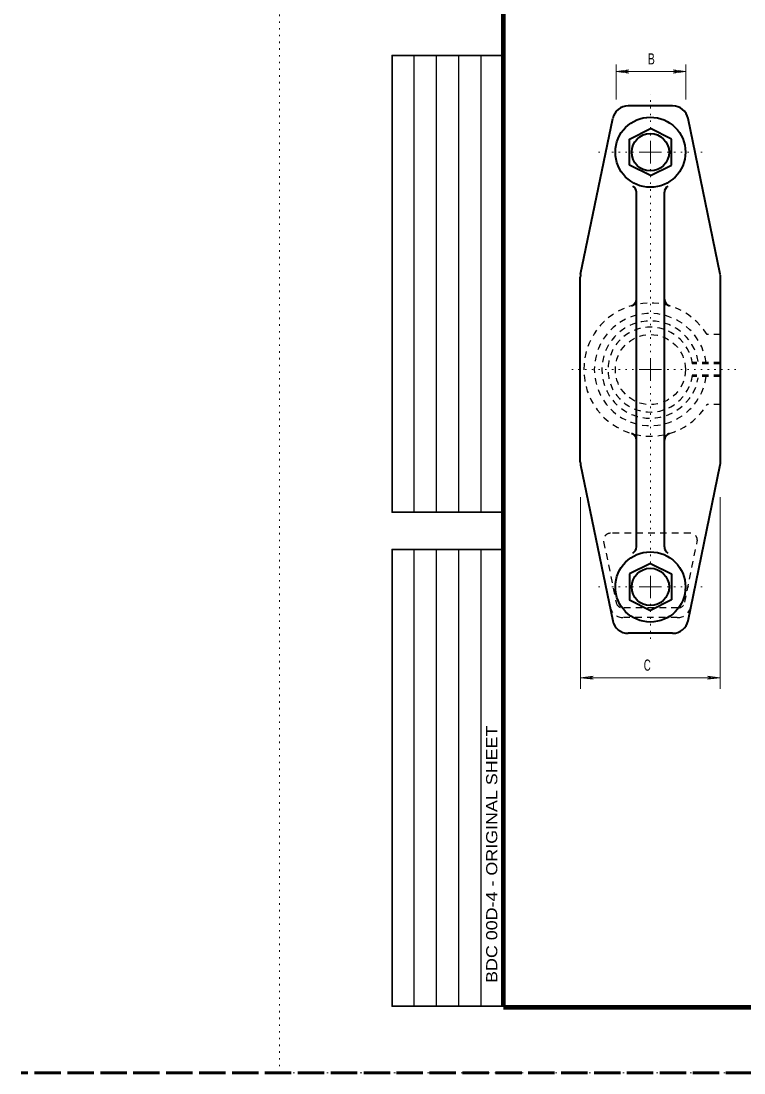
# Model space of a CAD drawing. Extents: x 312583 to 312854, y 144419 to 144597.
# Drawn here: x 312583.5 to 312632.9, y 144418.6 to 144490.5 of the extents above; entities that cross this region are included whole.
import ezdxf

# ---------------------------------------------------------------- set-up
doc = ezdxf.new("R2010")
doc.units = 0
doc.header["$LTSCALE"] = 0.3
for name, pattern in [('DOTTED', [1.5, 0.3, -1.2]), ('LONG_DASHED', [7.5, 6, -1.5]), ('SHORT_DASHED', [2.7, 1.5, -1.2])]:
    doc.linetypes.add(name, pattern=pattern)
for name, color, linetype, lineweight in [('1', 7, 'Continuous', 40), ('2', 7, 'Continuous', 13), ('62', 7, 'DOTTED', 13), ('63', 7, 'LONG_DASHED', 60)]:
    doc.layers.add(name, color=color, linetype=linetype, lineweight=lineweight)

msp = doc.modelspace()

# ---------------------------------------------------------------- linework, layer by layer
at = {"layer": '1', "lineweight": 25}
for p, q in [((312610.4087, 144456.901), (312610.4087, 144488.1192)), ((312611.9315, 144456.901), (312611.9315, 144488.1192)), ((312613.4543, 144456.901), (312613.4543, 144488.1192)), ((312614.9772, 144456.901), (312614.9772, 144488.1192)), ((312610.4087, 144423.1446), (312610.4087, 144454.3629)), ((312611.9315, 144423.1446), (312611.9315, 144454.3629)), ((312613.4543, 144423.1446), (312613.4543, 144454.3629)), ((312614.9772, 144423.1446), (312614.9772, 144454.3629))]:
    msp.add_line(p, q, dxfattribs=at)
at = {"layer": '1'}
for p, q in [((312628.0671, 144484.6708), (312625.0311, 144484.6708)), ((312621.7804, 144473.1632), (312623.9807, 144483.8122)), ((312631.3254, 144473.1632), (312629.1251, 144483.8122)), ((312627.9904, 144482.3938), (312626.5491, 144483.1145)), ((312627.9904, 144480.6228), (312627.9904, 144482.3938)), ((312626.5491, 144479.9022), (312625.1154, 144480.6228)), ((312626.5491, 144479.9022), (312627.9904, 144480.6228)), ((312625.5907, 144454.5332), (312625.5907, 144478.7752)), ((312627.5074, 144454.5332), (312627.5074, 144478.7752)), ((312621.7574, 144460.3368), (312621.7574, 144472.9638)), ((312631.3407, 144460.3368), (312631.3407, 144472.9638)), ((312621.7804, 144460.1452), (312623.9731, 144449.4885)), ((312629.1251, 144449.4885), (312631.3254, 144460.1452)), ((312626.5491, 144453.4062), (312625.1154, 144452.6855)), ((312626.5491, 144453.4062), (312627.9904, 144452.6855)), ((312627.9904, 144452.6855), (312627.9904, 144450.9068)), ((312627.9904, 144450.9068), (312626.5491, 144450.1938)), ((312628.0671, 144448.6298), (312625.0311, 144448.6298))]:
    msp.add_line(p, q, dxfattribs=at)
at = {"layer": '1', "linetype": 'SHORT_DASHED', "lineweight": 25}
for p, q in [((312631.3407, 144469.0462), (312630.4207, 144469.0462)), ((312631.3407, 144467.1295), (312629.4011, 144467.1295)), ((312631.3407, 144467.0375), (312629.4011, 144467.0375)), ((312631.3407, 144466.2708), (312629.4011, 144466.2708)), ((312631.3407, 144466.1712), (312629.4011, 144466.1712)), ((312631.3407, 144464.2545), (312630.4207, 144464.2545)), ((312629.2784, 144455.4685), (312623.8197, 144455.4685)), ((312623.3521, 144454.8935), (312624.2107, 144450.7458)), ((312628.8951, 144450.7458), (312629.7537, 144454.8935)), ((312628.4274, 144450.3625), (312624.6784, 144450.3625)), ((312628.3891, 144449.7032), (312624.7167, 144449.7032))]:
    msp.add_line(p, q, dxfattribs=at)
at = {"layer": '1', "lineweight": 158}
msp.add_line((312616.5, 144423.0846), (312849, 144423.0846), dxfattribs=at)
msp.add_lwpolyline([(312616.5, 144423.1446), (312616.5, 144585.0846), (312849, 144585.0846)], dxfattribs=at)
at = {"layer": '1', "lineweight": 35}
for points in [[(312616.5, 144456.901), (312608.8858, 144456.901), (312608.8858, 144488.1192), (312616.5, 144488.1192)], [(312616.5, 144423.1446), (312608.8858, 144423.1446), (312608.8858, 144454.3629), (312616.5, 144454.3629)]]:
    msp.add_lwpolyline(points, dxfattribs=at)
at = {"layer": '1'}
for points in [[(312625.1154, 144480.6228), (312625.1154, 144482.3938), (312626.5491, 144483.1145)], [(312625.1154, 144452.6855), (312625.1154, 144450.9145), (312626.5491, 144450.1938)]]:
    msp.add_lwpolyline(points, dxfattribs=at)
for centre, radius in [((312626.5491, 144481.5045), 2.3958), ((312626.5491, 144481.5045), 1.2773), ((312626.5491, 144451.7962), 2.3958), ((312626.5491, 144451.7962), 1.2773)]:
    msp.add_circle(centre, radius, dxfattribs=at)
at = {"layer": '1', "linetype": 'SHORT_DASHED', "lineweight": 25}
msp.add_circle((312626.5491, 144466.6503), 2.3958, dxfattribs=at)
at = {"layer": '1'}
for centre, radius, start, end in [((312625.0316, 144483.5927), 1.0781, 90, 168.33754), ((312628.0666, 144483.5927), 1.0781, 11.66246, 90), ((312625.1116, 144478.7732), 0.4792, 0, 60), ((312627.9866, 144478.7732), 0.4792, 120, 180), ((312622.7157, 144472.9656), 0.9583, 168.33293, 180), ((312630.3824, 144472.9656), 0.9583, 0, 11.66707), ((312625.1116, 144471.4739), 0.4792, 286.59504, 0), ((312627.9866, 144471.4739), 0.4792, 180, 253.40496), ((312625.1116, 144461.8268), 0.4792, 0, 73.40496), ((312627.9866, 144461.8268), 0.4792, 106.59504, 180), ((312622.7157, 144460.3387), 0.9583, 180, 191.64343), ((312630.3824, 144460.3387), 0.9583, 348.35657, 0), ((312625.1116, 144454.5275), 0.4792, 300, 0), ((312627.9866, 144454.5275), 0.4792, 180, 240), ((312625.0316, 144449.708), 1.0781, 191.65872, 270), ((312628.0665, 144449.708), 1.0781, 270, 348.34128)]:
    msp.add_arc(centre, radius, start, end, dxfattribs=at)
at = {"layer": '1', "linetype": 'SHORT_DASHED', "lineweight": 25}
for centre, radius, start, end in [((312626.5491, 144466.6503), 4.554, 31.74971, 328.25029), ((312626.5491, 144466.6503), 3.8333, 7.18188, 352.81924), ((312626.5491, 144466.6503), 3.3206, 9.58783, 350.40593), ((312626.5491, 144466.6503), 2.9011, 7.65517, 352.33031), ((312623.8189, 144454.9855), 0.4792, 90, 191.66303), ((312629.2792, 144454.9855), 0.4792, 348.33697, 90), ((312624.7141, 144450.6577), 0.9583, 191.66303, 270), ((312624.6744, 144450.8378), 0.4792, 191.66973, 270), ((312628.384, 144450.6577), 0.9583, 270, 348.33697), ((312628.4238, 144450.8378), 0.4792, 270, 348.33027)]:
    msp.add_arc(centre, radius, start, end, dxfattribs=at)
at = {"layer": '2'}
for p, q in [((312624.2031, 144485.1155), (312624.2031, 144487.4998)), ((312624.2031, 144487.0245), (312625.0694, 144487.1318)), ((312625.0694, 144487.1318), (312624.7934, 144487.0245)), ((312628.1054, 144487.1318), (312628.3814, 144487.0245)), ((312628.9717, 144487.0245), (312628.1054, 144487.1318)), ((312628.9717, 144485.1155), (312628.9717, 144487.4998)), ((312624.2031, 144487.0245), (312628.9717, 144487.0245)), ((312624.2031, 144487.0245), (312625.0694, 144486.9172)), ((312625.0694, 144486.9172), (312624.7934, 144487.0245)), ((312628.1054, 144486.9172), (312628.3814, 144487.0245)), ((312628.9717, 144487.0245), (312628.1054, 144486.9172)), ((312626.5491, 144481.5045), (312626.5491, 144482.2712)), ((312626.5491, 144481.5045), (312625.7824, 144481.5045)), ((312626.5491, 144481.5045), (312627.3157, 144481.5045)), ((312626.5491, 144481.5045), (312626.5491, 144480.7378)), ((312626.5491, 144466.6542), (312626.5491, 144467.4208)), ((312626.5491, 144466.6542), (312625.7824, 144466.6542)), ((312626.5491, 144466.6542), (312627.3157, 144466.6542)), ((312626.5491, 144466.6542), (312626.5491, 144465.8875)), ((312621.7804, 144457.9295), (312621.7804, 144444.8425)), ((312631.3254, 144457.9295), (312631.3254, 144444.8425)), ((312626.5491, 144451.7962), (312626.5491, 144452.5628)), ((312626.5491, 144451.7962), (312625.7824, 144451.7962)), ((312626.5491, 144451.7962), (312627.3157, 144451.7962)), ((312626.5491, 144451.7962), (312626.5491, 144451.0295)), ((312621.7804, 144445.5938), (312622.6467, 144445.7012)), ((312621.7804, 144445.5938), (312631.3254, 144445.5938)), ((312621.7804, 144445.5938), (312622.6467, 144445.4865)), ((312622.6467, 144445.7012), (312622.3707, 144445.5938)), ((312622.6467, 144445.4865), (312622.3707, 144445.5938)), ((312630.4591, 144445.7012), (312630.7351, 144445.5938)), ((312631.3254, 144445.5938), (312630.4591, 144445.7012)), ((312630.4591, 144445.4865), (312630.7351, 144445.5938)), ((312631.3254, 144445.5938), (312630.4591, 144445.4865))]:
    msp.add_line(p, q, dxfattribs=at)
at = {"layer": '2', "linetype": 'DOTTED'}
for p, q in [((312626.5491, 144482.6545), (312626.5491, 144485.4298)), ((312625.3991, 144481.5045), (312622.7081, 144481.5045)), ((312627.6991, 144481.5045), (312630.3364, 144481.5045)), ((312626.5491, 144480.3545), (312626.5491, 144467.7352)), ((312625.3991, 144466.6542), (312621.1824, 144466.6542)), ((312627.6991, 144466.6542), (312632.6211, 144466.6542)), ((312626.5491, 144465.5042), (312626.5491, 144453.0842)), ((312625.3991, 144451.7962), (312622.7081, 144451.7962)), ((312627.6991, 144451.7962), (312630.3364, 144451.7962)), ((312626.5491, 144450.6462), (312626.5491, 144448.0165))]:
    msp.add_line(p, q, dxfattribs=at)
at = {"layer": '62'}
msp.add_line((312601.2, 144418.5846), (312601.2, 144596.7846), dxfattribs=at)
msp.add_lwpolyline([(312601.2, 144418.5846), (312853.5, 144418.5846), (312853.5, 144596.7846)], dxfattribs=at)
at = {"layer": '63'}
msp.add_line((312851.75, 144418.5846), (312583.526, 144418.5846), dxfattribs=at)

# ---------------------------------------------------------------- texts
at = {"layer": '1', "width": 1.2}
msp.add_text('BDC 00D-4 - ORIGINAL SHEET', height=0.7614, rotation=90, dxfattribs=at).set_placement((312616.0832, 144424.7374))
at = {"layer": '2'}
for s, width, p in [('B', 0.7, (312626.3772, 144487.5046)), ('C', 0.65, (312626.0956, 144446.074))]:
    msp.add_text(s, height=0.76, dxfattribs=dict(at, width=width)).set_placement(p)

doc.saveas('drawing.dxf')
